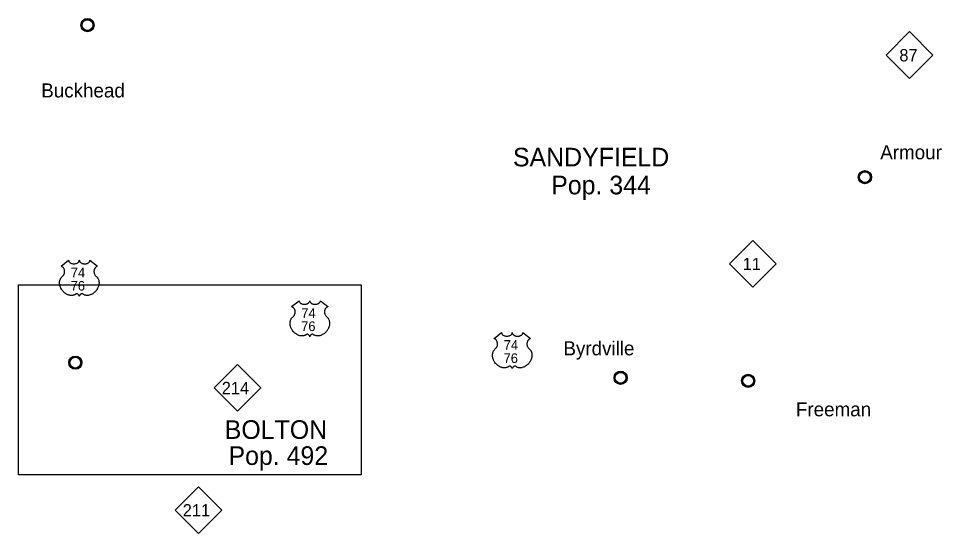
# Model space of a CAD drawing. Extents: x 5197761 to 5514561, y 1890130 to 2080942.
# Drawn here: x 5404629 to 5457192, y 2000039 to 2029358 of the extents above; entities that cross this region are included whole.
import ezdxf

# ---------------------------------------------------------------- set-up
doc = ezdxf.new("R2010")
doc.units = 0
for name, color, linetype in [('Exist Civil Demographics City Label', 7, 'Continuous'), ('Exist Civil Demographics Community CELL', 7, 'Continuous'), ('Exist Civil Demographics Community Label', 7, 'Continuous'), ('Exist Road Primary NC Shield CELL', 7, 'Continuous'), ('Exist Road Primary NC Shield Number Label', 7, 'Continuous'), ('Exist Road Primary US Shield CELL', 7, 'Continuous'), ('Exist Road Primary US Shield Number Label', 7, 'Continuous'), ('Map Preparation Inset Cut Line', 7, 'Continuous')]:
    doc.layers.add(name, color=color, linetype=linetype)

msp = doc.modelspace()

# ---------------------------------------------------------------- linework, layer by layer
at = {"layer": 'Exist Civil Demographics Community CELL'}
for points in [[(5408250, 2029031), (5408254, 2029053), (5408261, 2029079), (5408273, 2029108), (5408284, 2029131), (5408298, 2029154), (5408313, 2029175), (5408329, 2029192), (5408347, 2029210), (5408369, 2029229), (5408391, 2029243), (5408410, 2029255), (5408431, 2029265), (5408452, 2029274), (5408475, 2029281), (5408492, 2029286), (5408512, 2029289), (5408528, 2029292), (5408554, 2029293), (5408571, 2029292), (5408594, 2029291), (5408614, 2029288), (5408633, 2029284), (5408653, 2029279), (5408674, 2029271), (5408701, 2029259), (5408726, 2029245), (5408746, 2029231), (5408767, 2029215), (5408780, 2029202), (5408796, 2029185), (5408812, 2029166), (5408824, 2029148), (5408837, 2029128), (5408846, 2029107), (5408855, 2029087), (5408861, 2029067), (5408866, 2029049), (5408870, 2029024), (5408873, 2029006), (5408874, 2028982), (5408873, 2028959), (5408871, 2028936), (5408867, 2028914), (5408860, 2028889), (5408853, 2028866), (5408844, 2028846), (5408831, 2028822), (5408818, 2028800), (5408804, 2028782), (5408787, 2028763), (5408766, 2028743), (5408746, 2028726), (5408726, 2028712), (5408709, 2028702), (5408681, 2028689), (5408653, 2028679), (5408629, 2028673), (5408603, 2028668), (5408585, 2028666), (5408567, 2028665), (5408545, 2028665), (5408528, 2028666), (5408505, 2028669), (5408481, 2028674), (5408463, 2028680), (5408442, 2028687), (5408424, 2028695), (5408408, 2028704), (5408381, 2028720), (5408359, 2028737), (5408339, 2028755), (5408321, 2028775), (5408309, 2028791), (5408297, 2028807), (5408280, 2028836), (5408273, 2028850), (5408266, 2028866), (5408256, 2028899), (5408250, 2028927), (5408247, 2028948), (5408246, 2028973), (5408246, 2028992), (5408248, 2029018)], [(5452518, 2020374), (5452522, 2020397), (5452529, 2020423), (5452541, 2020452), (5452553, 2020475), (5452566, 2020498), (5452581, 2020518), (5452597, 2020536), (5452615, 2020554), (5452637, 2020572), (5452659, 2020587), (5452679, 2020599), (5452699, 2020608), (5452721, 2020618), (5452743, 2020625), (5452761, 2020629), (5452780, 2020632), (5452796, 2020635), (5452822, 2020636), (5452840, 2020636), (5452862, 2020635), (5452882, 2020632), (5452902, 2020628), (5452922, 2020622), (5452942, 2020615), (5452969, 2020603), (5452994, 2020589), (5453014, 2020575), (5453035, 2020559), (5453048, 2020546), (5453065, 2020529), (5453080, 2020510), (5453092, 2020491), (5453105, 2020471), (5453115, 2020451), (5453123, 2020431), (5453129, 2020411), (5453134, 2020392), (5453139, 2020368), (5453141, 2020349), (5453142, 2020325), (5453141, 2020302), (5453139, 2020279), (5453135, 2020258), (5453129, 2020233), (5453121, 2020210), (5453112, 2020189), (5453099, 2020165), (5453086, 2020144), (5453073, 2020125), (5453056, 2020106), (5453034, 2020086), (5453014, 2020070), (5452994, 2020056), (5452977, 2020046), (5452950, 2020033), (5452921, 2020022), (5452897, 2020016), (5452871, 2020011), (5452853, 2020009), (5452835, 2020008), (5452813, 2020008), (5452796, 2020010), (5452773, 2020013), (5452750, 2020018), (5452731, 2020023), (5452711, 2020031), (5452692, 2020039), (5452677, 2020048), (5452649, 2020064), (5452627, 2020081), (5452607, 2020099), (5452590, 2020119), (5452577, 2020134), (5452565, 2020151), (5452549, 2020179), (5452542, 2020194), (5452535, 2020210), (5452524, 2020242), (5452518, 2020271), (5452516, 2020291), (5452514, 2020317), (5452514, 2020335), (5452516, 2020361)], [(5407558, 2009816), (5407562, 2009838), (5407569, 2009865), (5407581, 2009894), (5407593, 2009916), (5407606, 2009939), (5407621, 2009960), (5407637, 2009977), (5407655, 2009996), (5407678, 2010014), (5407699, 2010029), (5407719, 2010040), (5407739, 2010050), (5407761, 2010059), (5407783, 2010067), (5407801, 2010071), (5407820, 2010074), (5407837, 2010077), (5407862, 2010078), (5407880, 2010078), (5407902, 2010077), (5407922, 2010074), (5407942, 2010070), (5407962, 2010064), (5407982, 2010056), (5408009, 2010045), (5408034, 2010031), (5408054, 2010016), (5408075, 2010000), (5408088, 2009988), (5408105, 2009970), (5408120, 2009952), (5408132, 2009933), (5408145, 2009913), (5408155, 2009892), (5408163, 2009872), (5408169, 2009852), (5408174, 2009834), (5408179, 2009810), (5408181, 2009791), (5408182, 2009767), (5408181, 2009744), (5408179, 2009721), (5408175, 2009699), (5408169, 2009675), (5408161, 2009651), (5408152, 2009631), (5408140, 2009607), (5408126, 2009586), (5408113, 2009567), (5408096, 2009548), (5408075, 2009528), (5408054, 2009512), (5408034, 2009498), (5408017, 2009488), (5407990, 2009475), (5407961, 2009464), (5407937, 2009458), (5407911, 2009453), (5407893, 2009451), (5407875, 2009450), (5407853, 2009450), (5407836, 2009452), (5407813, 2009455), (5407790, 2009460), (5407771, 2009465), (5407751, 2009473), (5407732, 2009480), (5407717, 2009489), (5407689, 2009506), (5407667, 2009523), (5407647, 2009541), (5407630, 2009560), (5407617, 2009576), (5407605, 2009593), (5407589, 2009621), (5407582, 2009635), (5407575, 2009651), (5407565, 2009684), (5407558, 2009712), (5407556, 2009733), (5407554, 2009758), (5407554, 2009777), (5407556, 2009803)], [(5438607, 2008956), (5438611, 2008978), (5438618, 2009005), (5438630, 2009034), (5438642, 2009057), (5438655, 2009079), (5438670, 2009100), (5438686, 2009117), (5438704, 2009136), (5438726, 2009154), (5438748, 2009169), (5438768, 2009180), (5438788, 2009190), (5438810, 2009199), (5438832, 2009207), (5438850, 2009211), (5438869, 2009214), (5438885, 2009217), (5438911, 2009218), (5438929, 2009218), (5438951, 2009217), (5438971, 2009214), (5438991, 2009210), (5439011, 2009204), (5439031, 2009196), (5439058, 2009185), (5439083, 2009171), (5439103, 2009157), (5439124, 2009140), (5439137, 2009128), (5439154, 2009110), (5439169, 2009092), (5439181, 2009073), (5439194, 2009053), (5439204, 2009033), (5439212, 2009012), (5439218, 2008992), (5439223, 2008974), (5439228, 2008950), (5439230, 2008931), (5439231, 2008907), (5439230, 2008884), (5439228, 2008861), (5439224, 2008839), (5439218, 2008815), (5439210, 2008791), (5439201, 2008771), (5439188, 2008747), (5439175, 2008726), (5439161, 2008707), (5439145, 2008688), (5439123, 2008668), (5439103, 2008652), (5439083, 2008638), (5439066, 2008628), (5439039, 2008615), (5439010, 2008604), (5438986, 2008598), (5438960, 2008593), (5438942, 2008591), (5438924, 2008590), (5438902, 2008590), (5438885, 2008592), (5438862, 2008595), (5438839, 2008600), (5438820, 2008605), (5438800, 2008613), (5438781, 2008621), (5438766, 2008629), (5438738, 2008646), (5438716, 2008663), (5438696, 2008681), (5438679, 2008700), (5438666, 2008716), (5438654, 2008733), (5438637, 2008761), (5438631, 2008775), (5438624, 2008791), (5438613, 2008824), (5438607, 2008852), (5438605, 2008873), (5438603, 2008898), (5438603, 2008917), (5438605, 2008943)], [(5445874, 2008780), (5445878, 2008802), (5445885, 2008829), (5445897, 2008858), (5445908, 2008880), (5445922, 2008903), (5445937, 2008924), (5445953, 2008941), (5445971, 2008960), (5445993, 2008978), (5446015, 2008993), (5446034, 2009004), (5446055, 2009014), (5446076, 2009023), (5446099, 2009031), (5446116, 2009035), (5446136, 2009038), (5446152, 2009041), (5446178, 2009042), (5446195, 2009042), (5446218, 2009041), (5446238, 2009038), (5446257, 2009034), (5446277, 2009028), (5446298, 2009020), (5446325, 2009009), (5446350, 2008995), (5446370, 2008980), (5446391, 2008964), (5446404, 2008952), (5446420, 2008934), (5446436, 2008916), (5446448, 2008897), (5446461, 2008877), (5446470, 2008856), (5446479, 2008836), (5446485, 2008816), (5446490, 2008798), (5446494, 2008774), (5446497, 2008755), (5446498, 2008731), (5446497, 2008708), (5446495, 2008685), (5446491, 2008663), (5446485, 2008639), (5446477, 2008615), (5446468, 2008595), (5446455, 2008571), (5446442, 2008550), (5446428, 2008531), (5446411, 2008512), (5446390, 2008492), (5446370, 2008476), (5446350, 2008462), (5446333, 2008452), (5446306, 2008439), (5446277, 2008428), (5446253, 2008422), (5446227, 2008417), (5446209, 2008415), (5446191, 2008414), (5446169, 2008414), (5446152, 2008416), (5446129, 2008419), (5446105, 2008424), (5446087, 2008429), (5446066, 2008437), (5446048, 2008444), (5446032, 2008453), (5446005, 2008470), (5445983, 2008487), (5445963, 2008505), (5445945, 2008524), (5445933, 2008540), (5445921, 2008557), (5445904, 2008585), (5445897, 2008599), (5445891, 2008615), (5445880, 2008648), (5445874, 2008676), (5445871, 2008697), (5445870, 2008722), (5445870, 2008741), (5445872, 2008767)]]:
    msp.add_lwpolyline(points, close=True, dxfattribs=at)
for centre, radius in [((5408560, 2028981), 377), ((5408559, 2028982), 307), ((5452829, 2020325), 377), ((5452828, 2020326), 307), ((5407869, 2009766), 377), ((5407868, 2009768), 307), ((5438918, 2008906), 377), ((5438917, 2008908), 307), ((5446184, 2008730), 377), ((5446183, 2008731), 307)]:
    msp.add_circle(centre, radius, dxfattribs=at)
at = {"layer": 'Exist Road Primary NC Shield CELL'}
for points in [[(5454040, 2027276), (5455372, 2028608), (5456704, 2027276), (5455372, 2025944)], [(5445118, 2015391), (5446450, 2016723), (5447782, 2015391), (5446450, 2014059)], [(5415769, 2008331), (5417101, 2009663), (5418433, 2008331), (5417101, 2006999)], [(5413547, 2001371), (5414879, 2002703), (5416211, 2001371), (5414879, 2000039)]]:
    msp.add_lwpolyline(points, close=True, dxfattribs=at)
at = {"layer": 'Exist Road Primary US Shield CELL'}
for points in [[(5407486, 2015595), (5407487, 2015577), (5407491, 2015556), (5407494, 2015545), (5407504, 2015525), (5407520, 2015500), (5407543, 2015477), (5407568, 2015456), (5407585, 2015445), (5407614, 2015429), (5407647, 2015415), (5407684, 2015405), (5407721, 2015397), (5407762, 2015393), (5407802, 2015392), (5407846, 2015395), (5407894, 2015404), (5407917, 2015410), (5407941, 2015419), (5407965, 2015428), (5407990, 2015442), (5408010, 2015455), (5408026, 2015466), (5408049, 2015488), (5408067, 2015510), (5408074, 2015523), (5408081, 2015535), (5408090, 2015561), (5408092, 2015572), (5408094, 2015595), (5408096, 2015576), (5408098, 2015563), (5408101, 2015551), (5408106, 2015539), (5408115, 2015520), (5408125, 2015505), (5408144, 2015483), (5408156, 2015472), (5408166, 2015463), (5408195, 2015443), (5408229, 2015426), (5408246, 2015419), (5408263, 2015413), (5408284, 2015406), (5408307, 2015401), (5408329, 2015397), (5408351, 2015394), (5408374, 2015392), (5408393, 2015392), (5408416, 2015392), (5408438, 2015393), (5408460, 2015396), (5408484, 2015400), (5408503, 2015404), (5408529, 2015411), (5408552, 2015419), (5408572, 2015428), (5408598, 2015442), (5408620, 2015455), (5408635, 2015468), (5408654, 2015485), (5408671, 2015505), (5408682, 2015520), (5408689, 2015535), (5408696, 2015551), (5408700, 2015568), (5408702, 2015583), (5408702, 2015596), (5409127, 2015257), (5409117, 2015253), (5409094, 2015242), (5409076, 2015231), (5409047, 2015211), (5409034, 2015199), (5409022, 2015188), (5409010, 2015175), (5409000, 2015163), (5408988, 2015146), (5408977, 2015129), (5408966, 2015110), (5408958, 2015094), (5408945, 2015060), (5408939, 2015038), (5408935, 2015020), (5408930, 2014982), (5408928, 2014964), (5408928, 2014946), (5408929, 2014927), (5408931, 2014909), (5408934, 2014890), (5408937, 2014874), (5408943, 2014853), (5408950, 2014830), (5408959, 2014807), (5408979, 2014770), (5409004, 2014732), (5409022, 2014711), (5409039, 2014693), (5409065, 2014671), (5409080, 2014658), (5409096, 2014642), (5409123, 2014611), (5409133, 2014597), (5409144, 2014580), (5409154, 2014563), (5409164, 2014545), (5409172, 2014529), (5409187, 2014493), (5409198, 2014458), (5409203, 2014439), (5409211, 2014397), (5409214, 2014377), (5409218, 2014336), (5409218, 2014287), (5409214, 2014240), (5409205, 2014186), (5409198, 2014153), (5409187, 2014115), (5409176, 2014082), (5409156, 2014034), (5409139, 2013998), (5409117, 2013957), (5409102, 2013932), (5409084, 2013906), (5409061, 2013875), (5409035, 2013842), (5409004, 2013808), (5408978, 2013783), (5408945, 2013753), (5408925, 2013736), (5408897, 2013715), (5408857, 2013689), (5408819, 2013666), (5408786, 2013650), (5408757, 2013637), (5408719, 2013623), (5408656, 2013605), (5408634, 2013601), (5408606, 2013597), (5408581, 2013594), (5408556, 2013593), (5408523, 2013593), (5408490, 2013595), (5408459, 2013600), (5408427, 2013606), (5408393, 2013616), (5408362, 2013628), (5408331, 2013644), (5408279, 2013677), (5408263, 2013685), (5408255, 2013687), (5408234, 2013688), (5408215, 2013684), (5408196, 2013676), (5408184, 2013670), (5408168, 2013660), (5408156, 2013650), (5408142, 2013636), (5408132, 2013625), (5408124, 2013616), (5408109, 2013593), (5408104, 2013581), (5408098, 2013567), (5408094, 2013546), (5408087, 2013573), (5408079, 2013590), (5408070, 2013605), (5408061, 2013619), (5408046, 2013636), (5408032, 2013649), (5408016, 2013662), (5407999, 2013672), (5407986, 2013679), (5407973, 2013684), (5407958, 2013687), (5407945, 2013688), (5407935, 2013688), (5407921, 2013685), (5407902, 2013671), (5407883, 2013659), (5407864, 2013646), (5407840, 2013634), (5407823, 2013626), (5407802, 2013618), (5407778, 2013610), (5407752, 2013603), (5407725, 2013598), (5407701, 2013594), (5407676, 2013592), (5407653, 2013591), (5407629, 2013591), (5407607, 2013593), (5407581, 2013595), (5407549, 2013600), (5407522, 2013606), (5407494, 2013613), (5407465, 2013622), (5407434, 2013634), (5407396, 2013651), (5407369, 2013665), (5407326, 2013689), (5407277, 2013724), (5407239, 2013754), (5407212, 2013779), (5407171, 2013820), (5407148, 2013847), (5407110, 2013895), (5407086, 2013930), (5407071, 2013956), (5407048, 2013997), (5407036, 2014023), (5407020, 2014060), (5407007, 2014095), (5406997, 2014128), (5406991, 2014148), (5406983, 2014185), (5406978, 2014211), (5406973, 2014246), (5406971, 2014284), (5406970, 2014318), (5406971, 2014347), (5406974, 2014380), (5406980, 2014415), (5406987, 2014446), (5406993, 2014468), (5407002, 2014494), (5407014, 2014524), (5407028, 2014552), (5407041, 2014575), (5407058, 2014600), (5407075, 2014622), (5407097, 2014645), (5407119, 2014667), (5407140, 2014684), (5407164, 2014708), (5407177, 2014722), (5407193, 2014743), (5407205, 2014762), (5407215, 2014778), (5407228, 2014803), (5407236, 2014822), (5407245, 2014851), (5407250, 2014871), (5407255, 2014896), (5407258, 2014921), (5407260, 2014951), (5407259, 2014976), (5407256, 2015006), (5407250, 2015034), (5407244, 2015058), (5407233, 2015087), (5407223, 2015107), (5407207, 2015135), (5407189, 2015161), (5407170, 2015182), (5407151, 2015201), (5407133, 2015215), (5407116, 2015227), (5407095, 2015240), (5407074, 2015251), (5407061, 2015256)], [(5420611, 2013291), (5420612, 2013274), (5420617, 2013253), (5420620, 2013242), (5420630, 2013221), (5420646, 2013197), (5420668, 2013173), (5420693, 2013152), (5420711, 2013141), (5420740, 2013126), (5420772, 2013112), (5420809, 2013101), (5420847, 2013094), (5420887, 2013089), (5420928, 2013088), (5420972, 2013092), (5421020, 2013101), (5421042, 2013107), (5421067, 2013115), (5421090, 2013125), (5421115, 2013138), (5421136, 2013151), (5421152, 2013163), (5421174, 2013185), (5421192, 2013207), (5421200, 2013220), (5421206, 2013232), (5421215, 2013257), (5421218, 2013269), (5421220, 2013292), (5421221, 2013272), (5421223, 2013260), (5421226, 2013248), (5421231, 2013235), (5421240, 2013217), (5421250, 2013202), (5421269, 2013180), (5421281, 2013169), (5421292, 2013160), (5421321, 2013140), (5421355, 2013123), (5421371, 2013116), (5421388, 2013110), (5421410, 2013103), (5421432, 2013098), (5421454, 2013094), (5421477, 2013091), (5421500, 2013089), (5421519, 2013088), (5421542, 2013089), (5421563, 2013090), (5421585, 2013092), (5421609, 2013096), (5421628, 2013101), (5421654, 2013108), (5421677, 2013116), (5421698, 2013125), (5421724, 2013138), (5421745, 2013152), (5421761, 2013164), (5421779, 2013181), (5421797, 2013202), (5421807, 2013217), (5421815, 2013232), (5421821, 2013248), (5421825, 2013265), (5421827, 2013280), (5421828, 2013293), (5422253, 2012954), (5422243, 2012950), (5422220, 2012939), (5422202, 2012928), (5422172, 2012907), (5422160, 2012896), (5422147, 2012884), (5422136, 2012872), (5422125, 2012860), (5422113, 2012843), (5422102, 2012826), (5422091, 2012807), (5422083, 2012791), (5422070, 2012756), (5422064, 2012735), (5422060, 2012716), (5422055, 2012678), (5422054, 2012660), (5422054, 2012643), (5422055, 2012624), (5422057, 2012606), (5422060, 2012587), (5422063, 2012570), (5422068, 2012550), (5422076, 2012526), (5422085, 2012503), (5422104, 2012466), (5422129, 2012429), (5422147, 2012408), (5422165, 2012390), (5422191, 2012368), (5422205, 2012355), (5422221, 2012339), (5422248, 2012308), (5422259, 2012293), (5422270, 2012277), (5422280, 2012260), (5422290, 2012242), (5422298, 2012226), (5422313, 2012190), (5422324, 2012154), (5422329, 2012136), (5422337, 2012094), (5422340, 2012073), (5422343, 2012033), (5422343, 2011983), (5422339, 2011937), (5422331, 2011882), (5422323, 2011850), (5422312, 2011812), (5422301, 2011779), (5422282, 2011730), (5422265, 2011695), (5422242, 2011654), (5422227, 2011629), (5422209, 2011602), (5422187, 2011572), (5422161, 2011539), (5422129, 2011505), (5422104, 2011479), (5422071, 2011450), (5422051, 2011433), (5422022, 2011411), (5421983, 2011385), (5421944, 2011363), (5421911, 2011346), (5421882, 2011334), (5421845, 2011319), (5421782, 2011302), (5421759, 2011297), (5421732, 2011293), (5421707, 2011291), (5421682, 2011289), (5421649, 2011289), (5421616, 2011292), (5421585, 2011296), (5421552, 2011303), (5421519, 2011313), (5421488, 2011325), (5421457, 2011340), (5421404, 2011374), (5421389, 2011382), (5421380, 2011384), (5421360, 2011385), (5421341, 2011381), (5421321, 2011373), (5421309, 2011367), (5421294, 2011356), (5421282, 2011347), (5421267, 2011333), (5421257, 2011322), (5421249, 2011312), (5421235, 2011289), (5421229, 2011278), (5421224, 2011264), (5421219, 2011243), (5421212, 2011269), (5421205, 2011287), (5421196, 2011302), (5421186, 2011315), (5421171, 2011332), (5421158, 2011345), (5421142, 2011358), (5421125, 2011368), (5421111, 2011376), (5421099, 2011380), (5421083, 2011384), (5421071, 2011385), (5421060, 2011385), (5421046, 2011382), (5421027, 2011368), (5421009, 2011355), (5420989, 2011343), (5420965, 2011330), (5420948, 2011322), (5420927, 2011314), (5420903, 2011306), (5420877, 2011299), (5420850, 2011294), (5420827, 2011290), (5420801, 2011288), (5420779, 2011287), (5420755, 2011288), (5420732, 2011289), (5420707, 2011292), (5420674, 2011296), (5420648, 2011302), (5420620, 2011310), (5420591, 2011319), (5420560, 2011331), (5420521, 2011348), (5420494, 2011361), (5420452, 2011386), (5420402, 2011420), (5420365, 2011451), (5420337, 2011476), (5420297, 2011517), (5420273, 2011544), (5420236, 2011592), (5420212, 2011627), (5420197, 2011652), (5420174, 2011694), (5420161, 2011719), (5420145, 2011757), (5420133, 2011792), (5420122, 2011824), (5420117, 2011845), (5420109, 2011881), (5420104, 2011907), (5420099, 2011943), (5420096, 2011980), (5420096, 2012015), (5420097, 2012043), (5420100, 2012077), (5420106, 2012112), (5420112, 2012142), (5420118, 2012164), (5420127, 2012191), (5420139, 2012220), (5420153, 2012248), (5420167, 2012272), (5420184, 2012297), (5420200, 2012318), (5420222, 2012342), (5420245, 2012363), (5420265, 2012380), (5420290, 2012404), (5420303, 2012419), (5420318, 2012439), (5420330, 2012458), (5420340, 2012475), (5420353, 2012500), (5420361, 2012518), (5420371, 2012547), (5420376, 2012567), (5420381, 2012593), (5420384, 2012617), (5420385, 2012648), (5420384, 2012673), (5420381, 2012702), (5420376, 2012730), (5420369, 2012755), (5420358, 2012783), (5420349, 2012804), (5420332, 2012832), (5420314, 2012858), (5420296, 2012879), (5420277, 2012898), (5420259, 2012912), (5420242, 2012924), (5420220, 2012937), (5420199, 2012947), (5420186, 2012953)], [(5432138, 2011474), (5432139, 2011457), (5432144, 2011436), (5432147, 2011425), (5432157, 2011404), (5432173, 2011380), (5432195, 2011356), (5432220, 2011335), (5432238, 2011324), (5432267, 2011309), (5432299, 2011295), (5432336, 2011284), (5432374, 2011277), (5432414, 2011272), (5432455, 2011272), (5432499, 2011275), (5432547, 2011284), (5432569, 2011290), (5432594, 2011298), (5432617, 2011308), (5432642, 2011322), (5432663, 2011335), (5432679, 2011346), (5432701, 2011368), (5432719, 2011390), (5432727, 2011403), (5432733, 2011415), (5432742, 2011440), (5432745, 2011452), (5432746, 2011475), (5432748, 2011455), (5432750, 2011443), (5432753, 2011431), (5432758, 2011418), (5432767, 2011400), (5432777, 2011385), (5432796, 2011363), (5432808, 2011352), (5432819, 2011343), (5432848, 2011323), (5432882, 2011306), (5432898, 2011299), (5432915, 2011293), (5432937, 2011286), (5432959, 2011281), (5432981, 2011277), (5433004, 2011274), (5433027, 2011272), (5433046, 2011272), (5433069, 2011272), (5433090, 2011273), (5433112, 2011276), (5433136, 2011280), (5433155, 2011284), (5433181, 2011291), (5433204, 2011299), (5433225, 2011308), (5433251, 2011322), (5433272, 2011335), (5433288, 2011347), (5433306, 2011364), (5433324, 2011385), (5433334, 2011400), (5433342, 2011415), (5433348, 2011431), (5433352, 2011448), (5433354, 2011463), (5433355, 2011476), (5433780, 2011137), (5433770, 2011133), (5433747, 2011122), (5433729, 2011111), (5433699, 2011090), (5433687, 2011079), (5433674, 2011067), (5433663, 2011055), (5433652, 2011043), (5433640, 2011026), (5433629, 2011009), (5433618, 2010990), (5433610, 2010974), (5433597, 2010939), (5433591, 2010918), (5433587, 2010899), (5433582, 2010862), (5433581, 2010843), (5433581, 2010826), (5433582, 2010807), (5433584, 2010789), (5433587, 2010770), (5433590, 2010753), (5433595, 2010733), (5433603, 2010709), (5433612, 2010686), (5433631, 2010650), (5433656, 2010612), (5433674, 2010591), (5433692, 2010573), (5433718, 2010551), (5433732, 2010538), (5433748, 2010522), (5433775, 2010491), (5433786, 2010476), (5433797, 2010460), (5433807, 2010443), (5433817, 2010425), (5433825, 2010409), (5433840, 2010373), (5433851, 2010337), (5433856, 2010319), (5433864, 2010277), (5433867, 2010256), (5433870, 2010216), (5433870, 2010167), (5433866, 2010120), (5433858, 2010065), (5433850, 2010033), (5433839, 2009995), (5433828, 2009962), (5433809, 2009913), (5433792, 2009878), (5433769, 2009837), (5433754, 2009812), (5433736, 2009785), (5433714, 2009755), (5433688, 2009722), (5433656, 2009688), (5433631, 2009662), (5433598, 2009633), (5433578, 2009616), (5433549, 2009595), (5433510, 2009568), (5433471, 2009546), (5433438, 2009529), (5433409, 2009517), (5433372, 2009502), (5433309, 2009485), (5433286, 2009480), (5433259, 2009476), (5433234, 2009474), (5433209, 2009472), (5433176, 2009472), (5433143, 2009475), (5433112, 2009479), (5433079, 2009486), (5433045, 2009496), (5433015, 2009508), (5432984, 2009523), (5432931, 2009557), (5432916, 2009565), (5432907, 2009567), (5432887, 2009568), (5432868, 2009564), (5432848, 2009556), (5432836, 2009550), (5432821, 2009540), (5432809, 2009530), (5432794, 2009516), (5432784, 2009505), (5432776, 2009496), (5432762, 2009472), (5432756, 2009461), (5432751, 2009447), (5432746, 2009426), (5432739, 2009452), (5432732, 2009470), (5432722, 2009485), (5432713, 2009498), (5432698, 2009515), (5432685, 2009528), (5432669, 2009541), (5432652, 2009552), (5432638, 2009559), (5432626, 2009563), (5432610, 2009567), (5432598, 2009568), (5432587, 2009568), (5432573, 2009565), (5432554, 2009551), (5432536, 2009538), (5432516, 2009526), (5432492, 2009513), (5432475, 2009505), (5432454, 2009497), (5432430, 2009489), (5432404, 2009482), (5432377, 2009477), (5432354, 2009473), (5432328, 2009471), (5432306, 2009470), (5432282, 2009471), (5432259, 2009472), (5432234, 2009475), (5432201, 2009479), (5432175, 2009486), (5432147, 2009493), (5432118, 2009502), (5432087, 2009514), (5432048, 2009531), (5432021, 2009545), (5431979, 2009569), (5431929, 2009603), (5431892, 2009634), (5431864, 2009659), (5431824, 2009700), (5431800, 2009727), (5431763, 2009775), (5431739, 2009810), (5431724, 2009835), (5431701, 2009877), (5431688, 2009902), (5431672, 2009940), (5431660, 2009975), (5431649, 2010007), (5431644, 2010028), (5431636, 2010065), (5431631, 2010090), (5431626, 2010126), (5431623, 2010163), (5431623, 2010198), (5431624, 2010226), (5431627, 2010260), (5431633, 2010295), (5431639, 2010326), (5431645, 2010347), (5431654, 2010374), (5431666, 2010403), (5431680, 2010432), (5431694, 2010455), (5431711, 2010480), (5431727, 2010501), (5431749, 2010525), (5431772, 2010547), (5431792, 2010563), (5431817, 2010588), (5431830, 2010602), (5431845, 2010622), (5431857, 2010641), (5431867, 2010658), (5431880, 2010683), (5431888, 2010702), (5431898, 2010730), (5431903, 2010750), (5431908, 2010776), (5431911, 2010801), (5431912, 2010831), (5431911, 2010856), (5431908, 2010885), (5431903, 2010914), (5431896, 2010938), (5431885, 2010966), (5431876, 2010987), (5431859, 2011015), (5431841, 2011041), (5431823, 2011062), (5431804, 2011081), (5431786, 2011095), (5431769, 2011107), (5431747, 2011120), (5431726, 2011130), (5431713, 2011136)]]:
    msp.add_lwpolyline(points, close=True, dxfattribs=at)
at = {"layer": 'Map Preparation Inset Cut Line'}
msp.add_lwpolyline([(5404629, 2014204), (5424152, 2014204), (5424152, 2003388), (5404629, 2003388)], close=True, dxfattribs=at)

# ---------------------------------------------------------------- texts
at = {"layer": 'Exist Civil Demographics City Label'}
for s, p in [('SANDYFIELD', (5432786, 2020937)), ('Pop. 344', (5434965, 2019348)), ('BOLTON', (5416377, 2005426)), ('Pop. 492', (5416589, 2003944))]:
    msp.add_text(s, height=1060, dxfattribs=at).set_placement(p)
at = {"layer": 'Exist Civil Demographics Community Label'}
for s, p in [('Buckhead', (5405926, 2024861)), ('Armour', (5453702, 2021342)), ('Byrdville', (5435662, 2010182)), ('Freeman', (5448900, 2006710))]:
    msp.add_text(s, height=800, dxfattribs=at).set_placement(p)
at = {"layer": 'Exist Road Primary NC Shield Number Label'}
for s, p in [('87', (5454789, 2026917)), ('11', (5445867, 2015032)), ('214', (5416205, 2007972)), ('211', (5413983, 2001012))]:
    msp.add_text(s, height=700, dxfattribs=at).set_placement(p)
at = {"layer": 'Exist Road Primary US Shield Number Label'}
for s, p in [('74', (5407609, 2014618)), ('76', (5407601, 2013867)), ('74', (5420735, 2012315)), ('76', (5420726, 2011563)), ('74', (5432262, 2010498)), ('76', (5432253, 2009746))]:
    msp.add_text(s, height=550, dxfattribs=at).set_placement(p)

doc.saveas('drawing.dxf')
